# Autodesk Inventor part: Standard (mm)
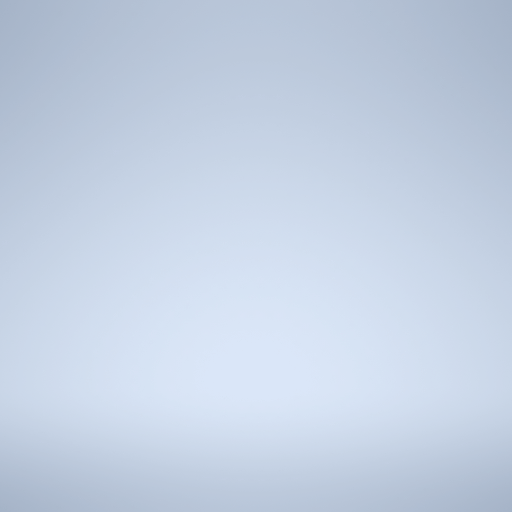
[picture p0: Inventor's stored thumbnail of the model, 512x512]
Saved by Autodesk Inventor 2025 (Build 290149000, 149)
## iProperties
Shininess: 64.0
Length Units: 11269
Angle Units: 11279
Time Units: 11290
Mass Units: 11283
Length Display Precision: 3
Angle Display Precision: 2
Compacted: True
Part Number: Standard (mm)
Document SubType Name: Modeling
Created: 2002-07
Density: 1 g/cm^3
Material: Generico
Appearance: Default
Density: 0.0
Volumn: 0.0
Area: 0.0
PropertySet Name: Model Information
Control State: 0
Master: False
Checked Out: False
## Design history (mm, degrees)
